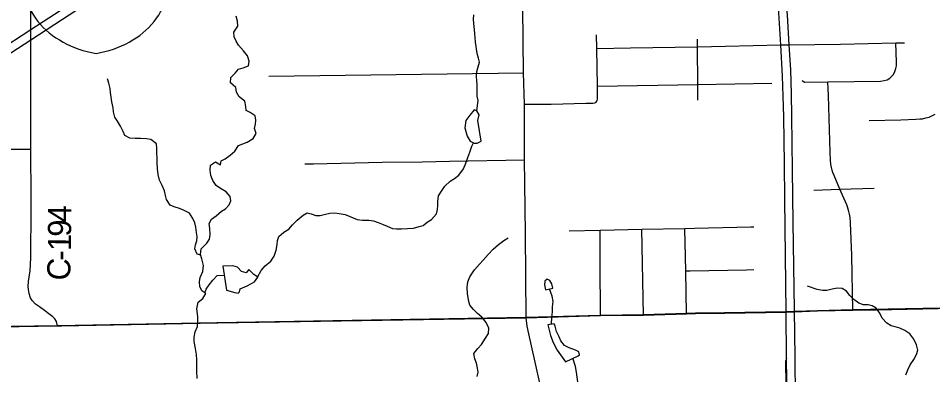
# Model space of a CAD drawing. Extents: x 0 to 34, y 0 to 22.
# Drawn here: x 4.531 to 6.774, y 15.737 to 16.611 of the extents above; entities that cross this region are included whole.
import ezdxf

# ---------------------------------------------------------------- set-up
doc = ezdxf.new("R2010")
doc.units = 0
for name, color, linetype in [('Default', 7, 'Continuous'), ('GM_X_City_Street', 7, 'Continuous'), ('GM_X_County_Road', 7, 'Continuous'), ('GM_X_County_Road_Text', 7, 'Continuous'), ('GM_X_Interchange_Ramps', 7, 'Continuous'), ('GM_X_Interstate_Route', 7, 'Continuous'), ('GM_X_Interstate_Shield', 7, 'Continuous'), ('GM_X_Minor_Lake', 7, 'Continuous'), ('GM_X_Minor_River', 7, 'Continuous'), ('GM_X_State_Route', 7, 'Continuous'), ('GM_X_Township_Road', 7, 'Continuous')]:
    doc.layers.add(name, color=color, linetype=linetype)

msp = doc.modelspace()

# ---------------------------------------------------------------- linework, layer by layer
at = {"layer": 'Default'}
for points in [[(8.4608, 15.4787), (8.4608, 15.9241), (8.2582, 15.9227), (7.5392, 15.9156), (7.3026, 15.9113), (7.0184, 15.9049), (6.9232, 15.9027), (6.5781, 15.8955), (6.4918, 15.8937), (6.4353, 15.8916), (6.4145, 15.8911), (6.2639, 15.8885), (6.1922, 15.8873), (6.1703, 15.8865), (6.065, 15.8836), (5.9591, 15.8823), (5.7768, 15.8771), (5.0185, 15.8642), (4.6273, 15.8569), (4.3446, 15.8524)], [(4.3446, 15.8524), (4.6273, 15.8569), (5.0185, 15.8642), (5.7768, 15.8771), (5.9591, 15.8823), (6.065, 15.8836), (6.1703, 15.8865), (6.1922, 15.8873), (6.2639, 15.8885), (6.4145, 15.8911), (6.4353, 15.8916), (6.4918, 15.8937), (6.5781, 15.8955), (6.9232, 15.9027)]]:
    msp.add_lwpolyline(points, dxfattribs=at)
at = {"layer": 'GM_X_City_Street'}
for p, q in [((5.1456, 16.469), (5.7708, 16.4775)), ((6.0652, 15.8831), (6.0612, 16.0937))]:
    msp.add_line(p, q, dxfattribs=at)
for points in [[(5.9491, 16.4053), (5.9507, 16.4075), (5.9513, 16.4094), (5.952, 16.4127), (5.9523, 16.4175), (5.952, 16.4441), (5.9503, 16.5366), (5.9495, 16.5702)], [(6.1984, 16.4102), (6.1982, 16.4311), (6.198, 16.4485), (6.1975, 16.5411), (6.1977, 16.5594)], [(5.9503, 16.5366), (6.0333, 16.5381), (6.1975, 16.5411), (6.266, 16.5422), (6.4018, 16.5458), (6.4223, 16.5457), (6.548, 16.5477), (6.6836, 16.5506), (6.7054, 16.5509)], [(6.4545, 16.4586), (6.4596, 16.4541), (6.5173, 16.4549), (6.6465, 16.4568), (6.6553, 16.4581), (6.6627, 16.4602), (6.669, 16.4637), (6.6744, 16.4686), (6.6779, 16.4731), (6.6818, 16.4802), (6.684, 16.4877), (6.6853, 16.4944), (6.6858, 16.5032), (6.6836, 16.5506)], [(5.952, 16.4441), (6.198, 16.4485), (6.3798, 16.4521)], [(6.5784, 15.8949), (6.5758, 16.0295), (6.5728, 16.1095), (6.5716, 16.1223), (6.5702, 16.1301), (6.5689, 16.1367), (6.5672, 16.1429), (6.5657, 16.1483), (6.564, 16.1536), (6.5534, 16.1775), (6.547, 16.1919), (6.5323, 16.2251), (6.5294, 16.2324), (6.5276, 16.2384), (6.526, 16.2448), (6.5247, 16.2523), (6.5237, 16.2626), (6.5232, 16.2825), (6.5188, 16.4212), (6.5173, 16.4549)], [(5.7728, 16.3999), (5.8388, 16.4006), (5.9233, 16.4028), (5.9356, 16.4028), (5.941, 16.403), (5.9458, 16.4036), (5.9491, 16.4053)], [(6.6189, 16.3603), (6.6966, 16.362), (6.7332, 16.3634), (6.7432, 16.3642), (6.7495, 16.3646), (6.7578, 16.3666), (6.7657, 16.3687), (6.7743, 16.3723), (6.7803, 16.3756)], [(5.2342, 16.2538), (5.255, 16.2538), (5.4235, 16.2582), (5.5221, 16.259), (5.5889, 16.2607), (5.7733, 16.2637)], [(6.4828, 16.1897), (6.547, 16.1919), (6.6307, 16.1944)], [(5.8827, 16.09), (5.9584, 16.0913), (6.0612, 16.0937), (6.1666, 16.0955), (6.1903, 16.0965), (6.3285, 16.0991), (6.3354, 16.0994)], [(5.9593, 15.8818), (5.9589, 16.0101), (5.9584, 16.0913)], [(6.1705, 15.886), (6.1692, 15.9913), (6.1666, 16.0955)], [(6.1692, 15.9913), (6.1798, 15.9919), (6.3175, 15.9941), (6.3354, 15.9951)]]:
    msp.add_lwpolyline(points, dxfattribs=at)
at = {"layer": 'GM_X_County_Road'}
for p, q in [((5.9593, 15.8818), (6.0652, 15.8831)), ((6.6359, 15.8961), (6.9234, 15.9021)), ((4.6374, 15.8565), (4.8929, 15.8613)), ((5.0207, 15.8636), (5.777, 15.8765)), ((5.777, 15.8765), (5.9593, 15.8818))]:
    msp.add_line(p, q, dxfattribs=at)
for points in [[(4.5621, 16.5183), (4.562, 16.5386), (4.562, 16.5585), (4.5617, 16.5838), (4.5622, 16.6348), (4.5622, 16.6736), (4.5617, 16.7594)], [(5.777, 15.8765), (5.7751, 16.0833), (5.7735, 16.2069), (5.7733, 16.2637), (5.7728, 16.3999), (5.7708, 16.4775), (5.7687, 16.6365)], [(4.6275, 15.8563), (4.6248, 15.8669), (4.6205, 15.8736), (4.6162, 15.8784), (4.6062, 15.8864), (4.5954, 15.8945), (4.5828, 15.9033), (4.5735, 15.9101), (4.5655, 15.9186), (4.5615, 15.9251), (4.558, 15.9359), (4.5559, 15.9455), (4.5554, 15.9533), (4.5566, 15.9656), (4.5582, 15.9756), (4.5607, 15.9912), (4.5615, 16.0068), (4.5617, 16.0246), (4.5617, 16.0371), (4.5625, 16.1303), (4.5625, 16.1689), (4.5618, 16.2896), (4.5623, 16.4106), (4.5621, 16.5183)], [(6.0652, 15.8831), (6.1705, 15.886), (6.1924, 15.8867), (6.2621, 15.8879)], [(6.2621, 15.8879), (6.2641, 15.888), (6.4147, 15.8905), (6.4355, 15.891), (6.492, 15.8931), (6.5784, 15.8949), (6.6359, 15.8961)], [(4.8929, 15.8613), (5.0187, 15.8636), (5.0207, 15.8636)], [(5.8717, 14.1), (5.8713, 14.2404), (5.872, 14.4243), (5.8732, 14.6187), (5.8739, 14.809), (5.875, 14.9557), (5.8744, 15.0978), (5.8759, 15.2554), (5.8769, 15.3727), (5.8762, 15.4088), (5.8752, 15.4255), (5.8739, 15.4356), (5.87, 15.4555), (5.8595, 15.5018), (5.8396, 15.592), (5.8151, 15.698), (5.7885, 15.8153), (5.784, 15.8367), (5.7797, 15.8558), (5.777, 15.8765)], [(4.3448, 15.8518), (4.6275, 15.8563), (4.6374, 15.8565)]]:
    msp.add_lwpolyline(points, dxfattribs=at)
at = {"layer": 'GM_X_Interchange_Ramps'}
msp.add_lwpolyline([(6.4161, 15.7761), (6.4147, 15.7735), (6.4137, 15.7698), (6.4131, 15.7649), (6.4139, 15.716)], dxfattribs=at)
at = {"layer": 'GM_X_Interstate_Route'}
for p, q in [((4.6393, 16.609), (4.8813, 16.767)), ((6.436, 15.8463), (6.4355, 15.8861))]:
    msp.add_line(p, q, dxfattribs=at)
for points in [[(6.4354, 15.896), (6.4325, 16.1103), (6.4307, 16.2396), (6.4291, 16.3704), (6.4281, 16.4267), (6.426, 16.4843), (6.4223, 16.5457), (6.4181, 16.6183), (6.4107, 16.702), (6.3949, 16.8952), (6.3912, 16.9349), (6.3749, 17.1382)], [(6.419, 14.1), (6.4211, 14.4229), (6.425, 14.9668), (6.4239, 15.0701), (6.4187, 15.5636), (6.4161, 15.7761), (6.4147, 15.8905), (6.4116, 16.1673), (6.4105, 16.2537), (6.4089, 16.369), (6.4076, 16.42), (6.4063, 16.4687), (6.4018, 16.5458), (6.3968, 16.6242), (6.3897, 16.7077), (6.3766, 16.863), (6.3715, 16.9335)], [(3.2883, 15.7557), (3.3742, 15.8104), (3.4252, 15.8444), (3.4615, 15.8686), (3.5692, 15.9376), (3.6732, 16.0058), (3.7824, 16.0765), (3.9368, 16.1769), (3.9615, 16.1929), (3.983, 16.207), (4.0953, 16.2802), (4.2473, 16.3787), (4.4606, 16.518), (4.4783, 16.5295), (4.5617, 16.5838), (4.8848, 16.7932), (4.8864, 16.7942)], [(4.4623, 16.4941), (4.4665, 16.4969), (4.482, 16.5069), (4.562, 16.5585), (4.6393, 16.609)], [(6.4355, 15.8861), (6.4355, 15.891), (6.4354, 15.896)], [(6.4379, 15.688), (6.437, 15.7716), (6.436, 15.8463)]]:
    msp.add_lwpolyline(points, dxfattribs=at)
at = {"layer": 'GM_X_Interstate_Shield'}
for centre, start_param, end_param in [((4.7664, 16.6989), 2.911027, 4.511031), ((4.6776, 16.6989), 4.913747, 6.513751)]:
    msp.add_ellipse(centre, major_axis=(0.2219, 0), ratio=0.8, start_param=start_param, end_param=end_param, dxfattribs=at)
at = {"layer": 'GM_X_Minor_Lake'}
for points in [[(5.6589, 16.3605), (5.6614, 16.3738), (5.6564, 16.3836), (5.6499, 16.3862), (5.6386, 16.3732), (5.6289, 16.3606), (5.6268, 16.3423), (5.6323, 16.3222), (5.64, 16.3094), (5.6499, 16.3045), (5.6571, 16.305), (5.6665, 16.3092)], [(5.6665, 16.3092), (5.6589, 16.3605)], [(5.0418, 15.9444), (5.0627, 15.9385), (5.0703, 15.937), (5.0737, 15.9397), (5.0755, 15.9473), (5.0929, 15.9543), (5.1106, 15.9648), (5.1185, 15.9758), (5.1086, 15.9826), (5.0971, 15.9946), (5.09, 15.9862), (5.0785, 15.9899), (5.0686, 16.0005), (5.0572, 16.0041), (5.0329, 16.0028)], [(5.0329, 16.0028), (5.0418, 15.9444)], [(5.8424, 15.9488), (5.8404, 15.9594), (5.8354, 15.9677), (5.8289, 15.9707), (5.8225, 15.9661), (5.8219, 15.9574), (5.8246, 15.9448)], [(5.8246, 15.9448), (5.8424, 15.9488)], [(5.9046, 15.7834), (5.9076, 15.7857), (5.9061, 15.7929), (5.8984, 15.797), (5.8828, 15.8025), (5.871, 15.8085), (5.8622, 15.8194), (5.8579, 15.8297), (5.8517, 15.8425), (5.8482, 15.8558), (5.8455, 15.8618), (5.8303, 15.8594), (5.8366, 15.8329), (5.8432, 15.8155), (5.8529, 15.7969), (5.8733, 15.7679)], [(5.8733, 15.7679), (5.9046, 15.7834)]]:
    msp.add_lwpolyline(points, dxfattribs=at)
at = {"layer": 'GM_X_Minor_River'}
for points in [[(4.9715, 15.8685), (4.9714, 15.8791), (4.9689, 15.8981), (4.9722, 15.9148), (4.9835, 15.9237), (4.991, 15.9355), (4.9814, 15.9423), (4.9768, 15.9529), (4.9756, 15.9642), (4.977, 15.9753), (4.9837, 15.9902), (4.9858, 16.0042), (4.9811, 16.0209), (4.9784, 16.0315), (4.9794, 16.0452), (4.9937, 16.0594), (5, 16.0693), (5.0022, 16.0808), (5.0009, 16.0956), (4.9993, 16.1073), (5.0049, 16.118), (5.017, 16.1265), (5.0298, 16.1376), (5.0396, 16.1434), (5.0486, 16.1534), (5.0523, 16.1633), (5.0507, 16.1735), (5.0411, 16.1856), (5.0274, 16.1938), (5.0167, 16.2006), (5.0082, 16.2127), (5.0039, 16.2252), (5.0016, 16.2381), (5.003, 16.251), (5.015, 16.2587), (5.0269, 16.2516), (5.0287, 16.2611), (5.0389, 16.2665), (5.0509, 16.2754), (5.0626, 16.2854), (5.0712, 16.2991), (5.0818, 16.303), (5.0928, 16.3073), (5.1075, 16.3162), (5.1146, 16.328), (5.1103, 16.3405), (5.1129, 16.3512), (5.1143, 16.3611), (5.1123, 16.3717), (5.0997, 16.3796), (5.0898, 16.3844), (5.0893, 16.3943), (5.0866, 16.4075), (5.0732, 16.4184), (5.0666, 16.4294), (5.065, 16.4412), (5.052, 16.4528), (5.0523, 16.4654), (5.0635, 16.4765), (5.0718, 16.4861), (5.0828, 16.4892), (5.096, 16.4943), (5.0978, 16.5061), (5.0935, 16.5186), (5.0839, 16.5314), (5.0717, 16.545), (5.0659, 16.5552), (5.0605, 16.5654), (5.0596, 16.5771), (5.0697, 16.5913), (5.0689, 16.6042), (5.0653, 16.6163)], [(5.6559, 16.3838), (5.6592, 16.4095), (5.6572, 16.4201), (5.6567, 16.4342), (5.6566, 16.4475), (5.6557, 16.4581), (5.6552, 16.468), (5.6563, 16.4805), (5.6592, 16.4916), (5.6629, 16.5034), (5.6601, 16.5132), (5.657, 16.5246), (5.6546, 16.5417), (5.653, 16.5523), (5.6521, 16.5637), (5.6512, 16.5736), (5.65, 16.583), (5.6488, 16.5979), (5.6483, 16.6089), (5.6486, 16.6195)], [(4.9788, 16.03), (4.9696, 16.0322), (4.9642, 16.0454), (4.966, 16.0553), (4.9693, 16.0653), (4.97, 16.0759), (4.9684, 16.0854), (4.9664, 16.099), (4.964, 16.1089), (4.9597, 16.1195), (4.9509, 16.1327), (4.9364, 16.1406), (4.9265, 16.1443), (4.9132, 16.1483), (4.9037, 16.1524), (4.8948, 16.1668), (4.8924, 16.1766), (4.8897, 16.188), (4.8839, 16.2005), (4.8773, 16.2141), (4.8745, 16.2281), (4.8725, 16.2414), (4.8716, 16.257), (4.8713, 16.2912), (4.8704, 16.3029), (4.8567, 16.3134), (4.8457, 16.3152), (4.8308, 16.3162), (4.8176, 16.3157), (4.8047, 16.3171), (4.7928, 16.3235), (4.7886, 16.3333), (4.782, 16.3462), (4.7747, 16.3587), (4.7681, 16.3688), (4.765, 16.3817), (4.7638, 16.3912), (4.761, 16.406), (4.759, 16.4178), (4.7577, 16.4292), (4.7565, 16.4387), (4.7534, 16.4515), (4.7498, 16.4621)], [(5.118, 15.9762), (5.1271, 15.9926), (5.1365, 16.0037), (5.1504, 16.0153), (5.159, 16.0275), (5.1638, 16.0424), (5.1664, 16.0557), (5.167, 16.0656), (5.1707, 16.0759), (5.1828, 16.0862), (5.1945, 16.094), (5.2035, 16.1047), (5.2152, 16.1154), (5.2299, 16.1277), (5.2397, 16.1335), (5.2499, 16.1313), (5.2614, 16.1276), (5.272, 16.1274), (5.2818, 16.1297), (5.2958, 16.1329), (5.308, 16.1334), (5.3182, 16.132), (5.3331, 16.1294), (5.343, 16.1257), (5.3529, 16.1213), (5.3628, 16.1176), (5.3757, 16.1154), (5.3909, 16.1156), (5.4026, 16.1138), (5.4144, 16.1101), (5.4262, 16.1052), (5.4358, 16.1008), (5.4491, 16.0956), (5.459, 16.0942), (5.4715, 16.0943), (5.4859, 16.0952), (5.5011, 16.0964), (5.5147, 16.1004), (5.5246, 16.1024), (5.5343, 16.1112), (5.5449, 16.1178), (5.5569, 16.1312), (5.5595, 16.1418), (5.5602, 16.1521), (5.5605, 16.1616), (5.5622, 16.1753), (5.5708, 16.1894), (5.5772, 16.199), (5.5904, 16.2113), (5.6009, 16.2178), (5.6119, 16.2259), (5.6231, 16.2416), (5.6291, 16.2553), (5.6339, 16.2694), (5.6387, 16.2828), (5.6439, 16.2969), (5.6477, 16.3056)], [(5.6573, 15.732), (5.6591, 15.7431), (5.6575, 15.7525), (5.6555, 15.7654), (5.6512, 15.7753), (5.6484, 15.7886), (5.6582, 15.8008), (5.6672, 15.8111), (5.6777, 15.8261), (5.6844, 15.8375), (5.6854, 15.8505), (5.6792, 15.8645), (5.6685, 15.8776), (5.6578, 15.887), (5.6482, 15.8968), (5.639, 15.907), (5.6367, 15.9165), (5.6331, 15.9347), (5.6326, 15.9506), (5.634, 15.9643), (5.6392, 15.9769), (5.6504, 15.9937), (5.6628, 16.0079), (5.6714, 16.0175), (5.6838, 16.0317), (5.6962, 16.0443), (5.7094, 16.0562), (5.7226, 16.0655), (5.7328, 16.0728)], [(4.9885, 15.9373), (4.9917, 15.9462), (4.9995, 15.9569), (5.0085, 15.9684), (5.0191, 15.9799), (5.0362, 15.9809)], [(6.7087, 15.7366), (6.7136, 15.7484), (6.7188, 15.761), (6.7278, 15.7744), (6.7349, 15.7862), (6.7382, 15.7965), (6.735, 15.8102), (6.7285, 15.8241), (6.7181, 15.8373), (6.7059, 15.8452), (6.6937, 15.8512), (6.6823, 15.8541), (6.6728, 15.8567), (6.6618, 15.8634), (6.6503, 15.875), (6.6449, 15.8879), (6.6361, 15.9), (6.6262, 15.906), (6.6159, 15.9078), (6.6046, 15.9077), (6.5931, 15.9125), (6.5813, 15.9215), (6.571, 15.9309), (6.5633, 15.9418), (6.5527, 15.9482), (6.5401, 15.9488), (6.5276, 15.9468), (6.5144, 15.9436), (6.5042, 15.9435), (6.4913, 15.9461), (6.4673, 15.9538)], [(5.8393, 15.8608), (5.84, 15.8781), (5.8414, 15.8907), (5.8421, 15.9036), (5.8431, 15.9161), (5.8411, 15.9294), (5.8345, 15.947)], [(4.9701, 15.7271), (4.9688, 15.7453), (4.969, 15.7632), (4.9689, 15.7731), (4.9681, 15.786), (4.966, 15.8012), (4.9625, 15.8178), (4.9624, 15.8292), (4.9653, 15.8418), (4.9705, 15.8548), (4.9715, 15.8685)], [(5.9162, 15.6786), (5.9115, 15.6919), (5.9072, 15.7055), (5.9041, 15.7195), (5.9025, 15.7305), (5.9008, 15.7427), (5.898, 15.7567), (5.8915, 15.7769)]]:
    msp.add_lwpolyline(points, dxfattribs=at)
at = {"layer": 'GM_X_State_Route'}
msp.add_line((6.436, 15.8463), (6.4355, 15.8861), dxfattribs=at)
for points in [[(6.4354, 15.896), (6.4325, 16.1103), (6.4307, 16.2396), (6.4291, 16.3704), (6.4281, 16.4267), (6.426, 16.4843), (6.4223, 16.5457), (6.4181, 16.6183), (6.4107, 16.702), (6.3949, 16.8952), (6.3912, 16.9349), (6.3749, 17.1382)], [(6.4355, 15.8861), (6.4355, 15.891), (6.4354, 15.896)], [(6.4379, 15.688), (6.437, 15.7716), (6.436, 15.8463)]]:
    msp.add_lwpolyline(points, dxfattribs=at)
at = {"layer": 'GM_X_Township_Road'}
msp.add_lwpolyline([(4.5055, 16.2901), (4.5618, 16.2896)], dxfattribs=at)

# ---------------------------------------------------------------- texts
at = {"layer": 'GM_X_County_Road_Text'}
for s, rotation, p in [('4', 89.6791, (4.6609, 16.11)), ('9', 89.6592, (4.6607, 16.075)), ('1', 89.6149, (4.6605, 16.04)), ('C', 86.141, (4.6571, 15.9662)), ('-', 89.6859, (4.6604, 16.0166))]:
    msp.add_text(s, height=0.0568, rotation=rotation, dxfattribs=at).set_placement(p)

doc.saveas('drawing.dxf')
